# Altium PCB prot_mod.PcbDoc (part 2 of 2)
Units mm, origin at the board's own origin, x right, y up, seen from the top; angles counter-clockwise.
Board outline 113 x 90 mm, 2 copper layers (Top Layer, Bottom Layer), stack 1.562 mm thick; 112 components, 43 nets, 249 pads, 37 vias.
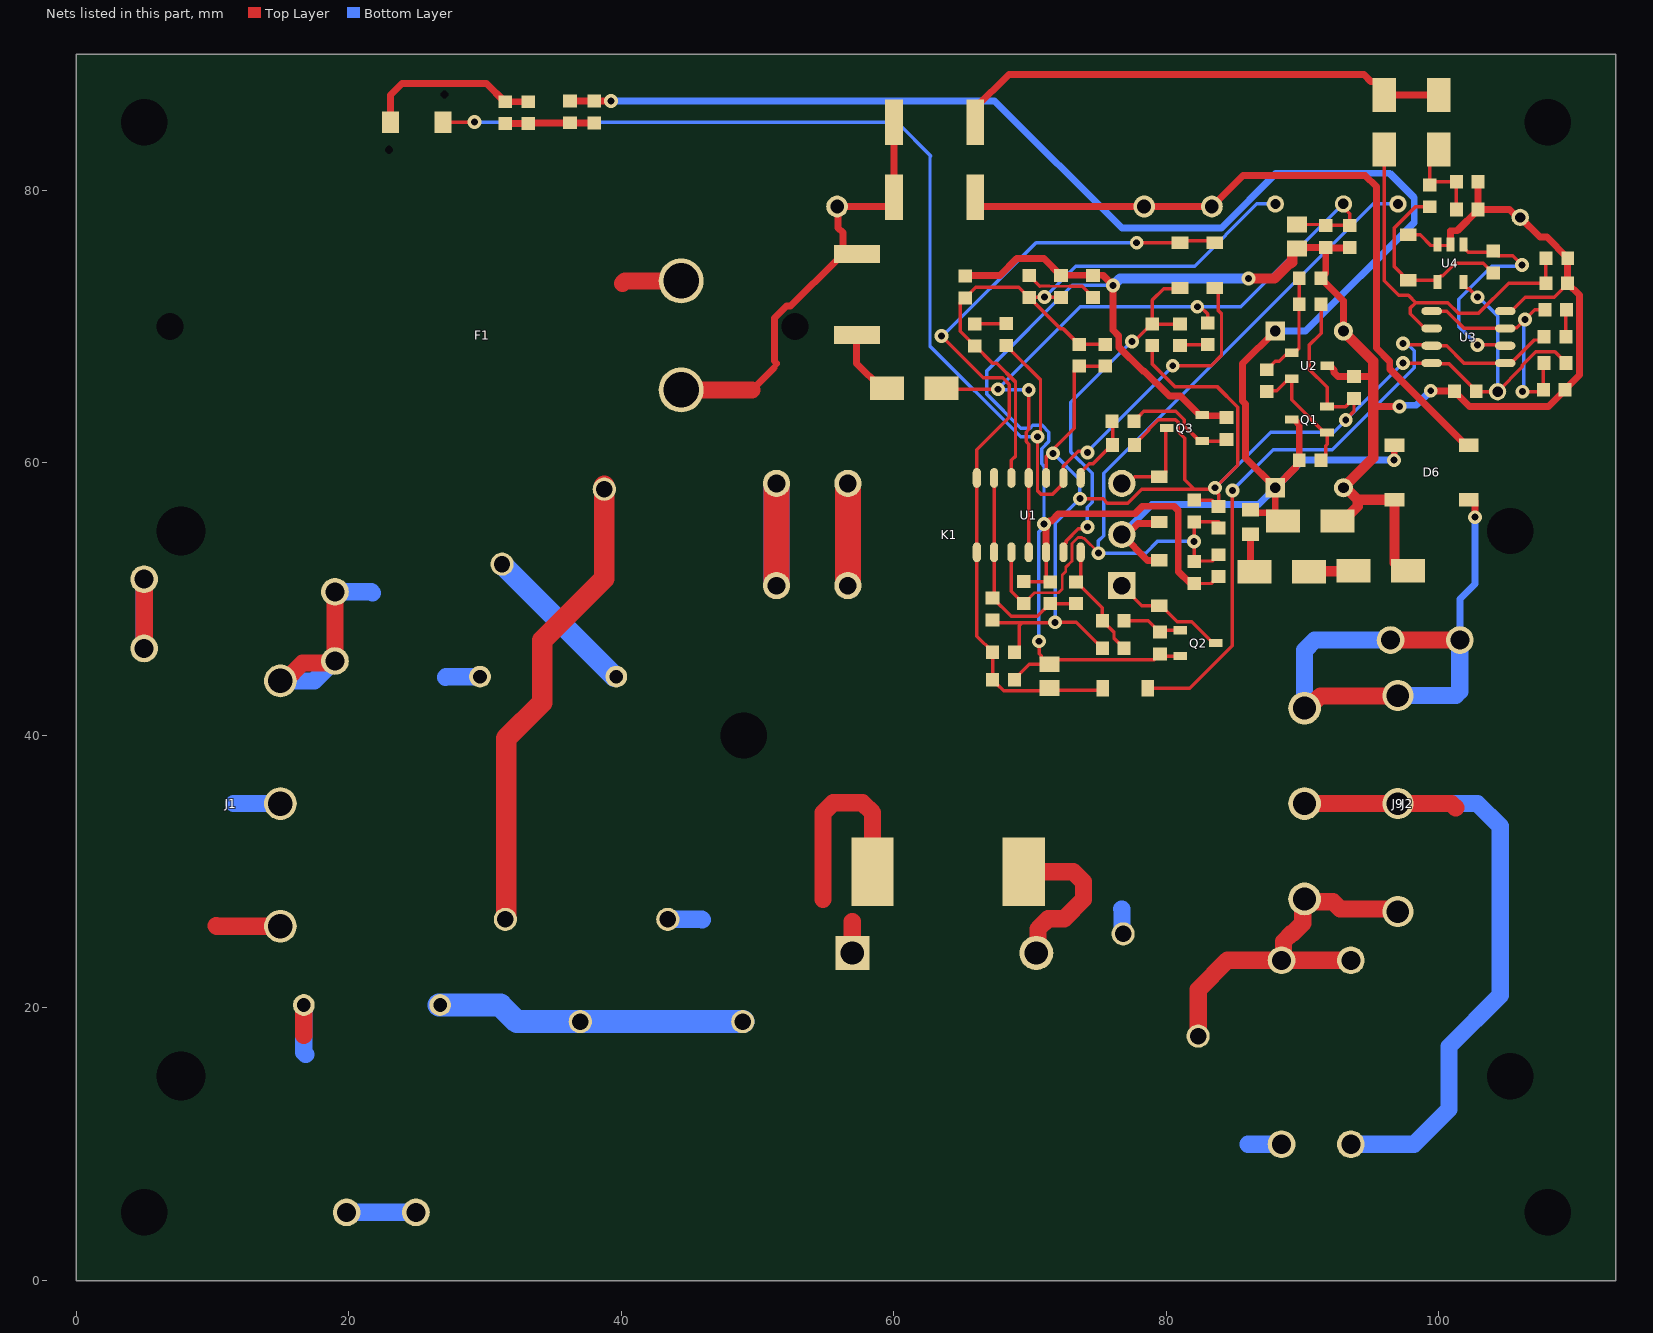
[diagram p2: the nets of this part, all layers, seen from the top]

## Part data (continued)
RV1 RV2 RV3 RV4: library part CMP-PROT-00005-2, "Thermally Protected Varistor 300 V RMS 775 V Clamp 10000 A 800 pF Radial Lead", Varistor Voltage=517V, Voltage Rating (AC)=300V
TP9 TP12 TP13 TP15 TP16: library part NOBOM-00007, "Test point, TH, 0.78mm (30mil) hole, 1.27mm (50 mil) pad", Manufacturer="New Horizons"
U1: library part CMP-ICANA-00000-1, "Quad low-power industrial grade standard comparator 14-SOIC -40 to 85", Case/Package=SOIC, Max Supply Voltage=30V, Min Supply Voltage=3V
U2: library part CMP-ICPWR-00000-1, "V-Ref Adjustable 1.24V to 24V 100mA 3-Pin SOT-23 T/R", Case/Package=SOT-23-3, Max Supply Voltage=25V, Tolerance=0.25%
U3: library part CMP-ICANA-00001-1, "Micropower CMOS dual voltage comparator, 9µA, 16V, -40, 0 to 125, 70°C, SO-8, Tape and Reel", Case/Package=SOIC, Max Supply Voltage=16V, Min Supply Voltage=2.7V
U4: library part CMP-ICANA-00002-2, "Op Amp Single Low Power Amplifier R-R I/O ±8V/16V 5-Pin SOT-23 T/R", Case/Package=SOT-23-5, Max Supply Voltage=16V, Min Supply Voltage=2.5V
Z1 Z6 Z7: library part CMP-NOBOM-00000-1, "Fiducial 1 mm copper, 3 mm solder mask, two footprint options."

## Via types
v1: diameter 1.016, hole 0.508, Top Layer to Bottom Layer, tented both sides, 36 vias
v2: diameter 1.6, hole 1.029, Top Layer to Bottom Layer, 1 vias

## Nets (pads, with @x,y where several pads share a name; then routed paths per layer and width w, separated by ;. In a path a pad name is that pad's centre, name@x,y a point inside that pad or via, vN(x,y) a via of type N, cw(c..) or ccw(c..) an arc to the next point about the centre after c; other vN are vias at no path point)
GND: GDT2.2 J1.3 J2.3 J7.1 J8.1 J9.3 | length 73.8
  Top Layer w1.27: 16.716,18 GDT2.2@16.716,20.216 ; J2.3@90.15,35 J9.3@97,35 100.926,35 101.242,34.683
  Bottom Layer w1.27: 11.564,35 J1.3@15,35 ; GDT2.2@16.716,20.216 16.716,16.738 16.862,16.592 ; J8.1@19.862,5 J8.1@24.942,5 ; 85.992,10 J7.1@88.46,10 ; J2.3@90.15,35 J9.3@97,35 102.843,35 104.518,33.325 104.518,20.941 100.75,17.174 100.75,12.573 98.177,10 J7.1@93.54,10
GND_PROT: C1.2 C12.2 C15.2 C16.2 C25.2 C119.2 C120.2 C121.2 C122.2 C123.2 C124.- C125.- D6.- D8.A D20.A D22.A Q2.2 Q3.2 R6.2 R9.2 R15.2 R17.1 R21.2 R24.1 R28.2 R31.2 R39.2 R44.2 R47.2 R64.2 TP12.1 U1.12 U2.3 U3.4 U4.2 U4.3 | length 204.6
  Top Layer w0.229: C120.2@65.251,73.673 C120.2@65.34,73.762
  Top Layer w0.254: C122.2@68.855,44.098 68.855,44.124 69.96,45.229 C1.2@71.423,45.229 ; C121.2@69.538,51.293 R9.2@71.469,51.293 ; v1(70.67,46.909) 70.67,45.982 70.815,45.837 70.815,45.682 C1.2@71.19,45.307 ; U1.12@71.18,54.133 U1.12@71.18,53.44 71.18,51.581 R9.2@71.469,51.293 ; R9.2@71.496,51.265 R9.2@71.469,51.293 ; C1.2@71.96,45.562 79.107,45.562 79.368,45.822 Q2.2@81.346,45.822 ; R15.2@72.25,73.767 R15.2@72.592,73.767 ; R28.2@82.046,51.149 83.303,51.149 83.811,51.657 R31.2@83.836,51.657 ; D20.A@97.747,76.725 98.633,76.725 99.407,75.951 U4.2@100.856,75.951 ; U3.4@104.876,71.133 105.306,71.133 106.33,72.157 108.474,72.157 C16.2@109.105,72.788
  Top Layer w0.508: C120.2@65.34,73.762 67.791,73.762 69.028,74.999 71.018,74.999 R15.2@72.25,73.767 ; U1.12@71.18,54.133 71.18,55.52 v1@71.403,55.742 ; 71.57,55.742 72.095,56.267 77.696,56.267 78.245,56.816 80.583,56.816 80.881,56.518 80.881,52.018 R28.2@81.765,51.134 ; R15.2@72.592,73.767 75.348,73.767 v1(76.096,73.019) 76.096,69.734 76.513,69.316 76.513,68.514 78.277,66.751 78.374,66.751 80.228,64.896 81.044,64.896 82.393,63.547 82.593,63.547 82.685,63.455 84.29,63.455 R24.1@84.421,63.325 ; C123.2@90.101,75.791 R44.2@91.705,75.791 ; R44.2@91.705,75.816 R44.2@91.705,75.791 ; U2.3@91.8,67.125 92,67.125 92.302,66.822 92.302,66.622 92.6,66.325 C119.2@93.775,66.325 95.051,66.325 95.201,66.175 ; C124.-@93,69.669 93,71.894 91.36,73.534 R6.2@91.36,73.559 91.36,73.584 91.705,73.929 R44.2@91.705,75.765 ; C15.2@93.383,75.765 R44.2@91.705,75.765 ; 95.201,63.98 95.354,64.133 v1(97.127,64.133) ; v1(99.407,65.291) 99.429,65.269 101.125,65.269 C25.2@101.147,65.247 101.147,65.222 102.237,64.133 108.058,64.133 109.274,65.349 R64.2@109.274,65.374 109.274,65.399 110.31,66.435 110.31,72.303 109.453,73.161 C16.2@109.453,73.186 109.456,73.189 109.456,75.005 R47.2@109.459,75.008 109.459,75.033 107.932,76.561 107.428,76.561 TP12.1@105.975,78.014 105.769,78.014 105.194,78.588 C12.2@102.887,78.588 ; U4.2@100.856,75.951 U4.2@100.856,76.026 100.856,77.031 101.354,77.031 102.887,78.563 C12.2@102.887,78.588 ; R39.2@102.887,80.62 C12.2@102.887,78.588 ; R44.2@91.705,75.765 R44.2@91.705,75.791
  Top Layer w0.762: v1(86.035,73.526) 87.93,73.526 89.055,74.651 89.156,74.651 89.237,74.731 89.237,75.542 89.436,75.741 C123.2@89.591,75.741 ; C123.2@89.591,75.791 C123.2@90.101,75.791 ; D22.A@92.56,55.743 92.96,55.743 94.043,56.826 94.043,57.304 ; C124.-@93,69.669 95.201,67.468 95.201,66.175 95.201,63.98 95.201,60.376 C125.-@93,58.175 93.173,58.175 94.043,57.304 ; D8.A@97.748,52.087 97.348,52.087 96.751,52.684 D6.-@96.751,57.304 94.043,57.304
  Bottom Layer w0.254: v1@70.628,46.909 70.628,54.899 71.028,55.299 v1(71.028,55.505) 71.028,59.773 70.878,59.923 70.878,60.345 70.867,60.356 70.867,61.047 71.388,61.569 71.388,62.261 70.899,62.75 70.207,62.75 70.008,62.55 69.32,62.55 66.813,65.056 66.813,66.721 73.11,73.019 v1(76.096,73.019)
  Bottom Layer w0.508: v1(97.127,64.133) 97.224,64.23 98.346,64.23 v1(99.407,65.291)
  Bottom Layer w0.762: v1(76.096,73.019) 76.603,73.526 v1(86.035,73.526)
input_ok: C1.1 C122.1 D3.A D4.A D5.A R5.2 U1.7 U1.8 | length 61.7
  Top Layer w0.254: v1(63.5,69.319) 66.581,66.237 67.994,66.237 68.483,65.748 68.483,63.352 66.1,60.969 U1.7@66.1,58.89 ; U1.7@66.1,58.565 U1.8@66.1,53.44 66.1,47.284 67.255,46.13 R5.2@67.255,46.105 ; R5.2@67.255,45.953 67.255,44.074 67.603,43.726 67.619,43.726 68.073,43.272 71.215,43.272 C1.1@71.423,43.479 ; C1.1@71.423,43.302 75.18,43.302 D4.A@75.332,43.454 ; D5.A@83.8,76.262 83.8,76.287 81.142,76.287 D3.A@81.006,76.151 v1(77.831,76.151) ; v1(77.831,76.151) 77.831,75.853 77.682,76.002 77.649,76.036 77.764,76.151 v1(77.831,76.151)
  Bottom Layer w0.254: v1(63.5,69.319) 63.61,69.319 70.442,76.151 v1(77.831,76.151)
L2: J2.1 J3.1 J9.1 L1.2 L2.2 RV2.1 | length 40
  Top Layer w1.27: L1.2@69.55,30 73.177,30 73.921,29.256 73.921,27.958 72.508,26.546 71.335,26.546 70.591,25.802 70.591,24.163 L2.2@70.464,24.036 ; RV2.1@82.338,17.934 82.338,21.35 84.488,23.5 J3.1@88.46,23.5 ; J3.1@93.54,23.5 J3.1@88.46,23.5 ; J9.1@97,27.075 96.816,27.259 92.76,27.259 92.236,27.784 90.366,27.784 J2.1@90.15,28 90.023,27.873 90.023,26.221 89.279,25.477 89.204,25.477 88.606,24.879 88.606,23.646 J3.1@88.46,23.5
LFUSED: C5.1 F1.1 K1.NO R2.1 R3.1 R10.1 RV1.2 RV3.1 | length 82.7
  Top Layer w0.508: 49.599,65.35 51.226,66.977 ; 51.416,67.295 51.246,67.465 51.246,70.623 52.127,71.504 52.439,71.504 55.864,74.929 56.265,74.929 R3.1@56.661,75.325 ; R3.1@57.303,75.325 56.972,75.325 R3.1@56.661,75.325 ; R10.1@60.025,85 R2.1@60.025,79.5 60.025,79.205 59.629,78.809 C5.1@55.85,78.809 55.928,78.731 55.928,77.247 56.265,76.91 56.265,75.721 R3.1@56.661,75.325
  Top Layer w1.27: F1.1@44.4,65.35 49.599,65.35
  Top Layer w1.524: RV3.1@31.538,26.469 31.538,26.658 31.563,26.683 31.563,39.778 34.207,42.422 34.207,46.969 38.762,51.524 RV1.2@38.762,58.297
  Top Layer w1.905: K1.NO@51.398,58.493 K1.NO@51.398,50.993 K1.NO@51.416,50.975
  Bottom Layer w1.905: K1.NO@51.398,50.993 K1.NO@51.398,58.493
LINE: F1.2 J1.1 J4.1 | length 19.3
  Top Layer w1.27: J4.1@5,46.381 J4.1@5,51.461 ; 10.285,26.04 10.324,26 J1.1@15,26 ; 40.093,73.162 40.28,73.35 F1.2@44.4,73.35
  Bottom Layer w1.27: J4.1@5,46.381 J4.1@5,51.461
LPROT: K1.COM L1.1 L2.1 | length 32.4
  Top Layer w0.254: 56.964,26.342 57.122,26.5
  Top Layer w1.27: 54.819,27.978 54.819,34.324 55.563,35.068 57.706,35.068 58.45,34.324 L1.1@58.45,30 ; L2.1@56.964,24.036 56.964,26.342
  Top Layer w1.905: K1.COM@56.638,50.993 K1.COM@56.638,58.493
  Bottom Layer w1.905: K1.COM@56.638,50.993 K1.COM@56.638,58.493
NC.MOV5: GDT2.1 RV3.2 RV4.2 | length 22.8
  Bottom Layer w1.7: GDT2.1@26.629,20.215 31.139,20.215 32.354,19 RV3.2@37.004,19 RV4.2@48.926,19
NetC5_2: C5.2 D6.AC1 R2.2 | length 53.1
  Top Layer w0.508: R2.2@65.975,79.5 65.975,79.205 66.371,78.809 v2(78.384,78.809) C5.2@83.35,78.809 85.641,81.1 94.6,81.1 95.419,80.281 95.419,73.114 95.435,73.098 95.435,68.415 96.401,67.449 96.401,66.879 101.976,61.304 D6.AC1@102.201,61.304
NetC6_2: C6.2 Q2.1 R17.2 | length 4.9
  Top Layer w0.254: C6.2@76.908,48.446 C6.2@76.908,48.421 78.669,48.421 79.518,47.572 R17.2@79.543,47.572 79.693,47.722 Q2.1@81.346,47.722
NetC7_2: C7.2 Q3.1 R24.2 | length 8.3
  Top Layer w0.254: C7.2@77.632,63.065 77.632,63.09 77.98,63.438 78.005,63.438 78.354,63.787 80.708,63.787 81.32,63.175 81.32,62.72 82.439,61.601 Q3.1@82.639,61.601 84.297,61.601 R24.2@84.421,61.725
NetC118_1: C118.1 Q1.1 R20.1 U2.2 | length 9.6
  Top Layer w0.254: C118.1@87.38,65.234 87.433,65.287 88.112,65.287 89,66.175 U2.2@89.2,66.175 89.2,64.624 91.6,62.225 Q1.1@91.8,62.225 91.8,61.356 91.708,61.264 91.708,60.544 R20.1@91.36,60.196
NetC118_2: C118.2 R6.1 R13.2 U2.1 | length 8.2
  Top Layer w0.254: C118.2@87.38,66.834 87.405,66.834 87.753,67.182 87.753,67.207 88.003,67.456 88.293,67.456 88.739,67.902 89.227,67.902 89.74,68.415 89.74,71.631 R13.2@89.76,71.652 R6.1@89.76,73.559
NetD8_K: D8.K D9.A | length 3.3
  Top Layer w0.762: D9.A@90.476,52.013 90.513,52.05 93.711,52.05 D8.K@93.748,52.087
NetD9_K: D9.K R181.2 | length 2.9
  Top Layer w0.508: R181.2@86.179,54.76 86.179,52.311 D9.K@86.476,52.013
NetD20_K: D20.K R50.2 R59.1 U4.4 | length 15.2
  Top Layer w0.254: R50.2@99.331,78.795 98.288,78.795 96.714,77.221 96.714,74.439 97.265,73.888 97.265,73.736 97.595,73.405 D20.K@97.747,73.405 99.852,73.405 99.906,73.351 99.906,73.501 100.129,73.724 100.279,73.724 101.206,74.651 101.681,74.651 103.26,74.651 103.975,73.935 R59.1@104,73.935 R59.1@104.292,73.643
NetD57_A: D57.A R3.2 | length 5
  Top Layer w0.254: D57.A@59.1,65.477 D57.A@59.5,65.477
  Top Layer w0.508: R3.2@57.282,69.354 57.282,67.295 D57.A@59.1,65.477
NetD58_A: D58.A D59.K R10.2 | length 36.9
  Top Layer w0.508: R10.2@65.975,85 65.975,86.025 68.45,88.5 94.5,88.5 95.004,87.996 95.404,87.996 96,87.4 D58.A@96,87 D59.K@100,87
NetD60_A: D60.A R48.2 R49.2 | length 13
  Top Layer w0.508: D60.A@23.068,85 23.068,87 23.909,87.841 30.117,87.841 31.461,86.497 R48.2@31.486,86.497 R49.2@33.171,86.497
NetGDT1_2: GDT1.2 RV1.1 | length 11.8
  Bottom Layer w1.524: RV1.1@31.263,52.567 39.503,44.326 39.63,44.326 GDT1.2@39.645,44.312
NetR4_1: R4.1 R8.1 | length 2.3
  Top Layer w0.254: R4.1@65.956,70.179 R4.1@65.981,70.179 ; R4.1@65.956,70.211 R8.1@68.258,70.211
NetR7_2: R7.2 R9.1 R12.1 U1.6 U1.9 | length 16
  Top Layer w0.254: U1.6@67.37,58.959 67.37,50.197 R7.2@67.255,50.081 67.28,50.081 68.629,48.732 70.538,48.732 71.471,49.665 R9.1@71.496,49.665 R12.1@73.376,49.665
NetR11_1: R11.1 R21.1 | length 5.2
  Top Layer w0.203: 70.717,72.956 70.722,72.956 70.742,72.976 71.413,72.976 71.433,72.956 72.907,72.956
  Top Layer w0.254: R11.1@70.052,73.622 70.717,72.956 ; 72.907,72.956 72.913,72.95 73.841,72.95 R21.1@74.624,72.167
NetR26_1: R26.1 R27.2 | length 2.1
  Top Layer w0.254: R26.1@81.007,68.597 81.084,68.673 R27.2@83.039,68.673
NetR48_1: R48.1 R49.1 R52.2 R56.2 | length 6.6
  Top Layer w0.508: R48.1@31.486,84.897 R49.1@33.171,84.897 33.201,84.928 36.22,84.928 R56.2@36.25,84.958 ; R56.2@36.25,84.943 R52.2@38.014,84.943
NetR54_1: R54.1 R58.1 | length 2.1
  Top Layer w0.254: R58.1@109.325,69.133 R58.1@109.381,69.189 ; R58.1@109.325,69.267 109.325,71.165 R54.1@109.381,71.221
NEUT: D6.AC2 GDT1.1 J1.2 J2.2 J5.1 J6.1 J9.5 RV2.2 RV4.1 | length 66.5
  Top Layer w0.508: D6.AC2@102.656,57.208 102.659,57.205 102.659,56.016 v1(102.663,56.013)
  Top Layer w1.27: J1.2@15,44 15.306,44 16.62,45.314 18.854,45.314 J6.1@19,45.46 J6.1@19,50.54 ; J2.2@90.15,42 90.421,42 91.313,42.893 96.968,42.893 J9.5@97,42.925 ; J5.1@96.46,47 J5.1@101.54,47
  Bottom Layer w0.508: 101.242,42.925 101.54,43.222 ; J5.1@101.54,47 101.54,50 102.663,51.123 v1(102.663,56.013) v1@102.8,56.013
  Bottom Layer w1.27: J1.2@15,44 17.475,44 18.935,45.46 J6.1@19,45.46 ; J6.1@19,50.54 21.655,50.54 21.75,50.445 ; 27.116,44.277 27.152,44.312 GDT1.1@29.645,44.312 ; RV4.1@43.426,26.5 45.925,26.5 45.956,26.469 ; 76.738,27.26 76.756,27.242 76.756,25.516 RV2.2@76.838,25.434 ; J2.2@90.15,42 90.15,46.256 90.894,47 J5.1@96.46,47 ; J9.5@97,42.925 101.242,42.925 ; 101.54,43.222 J5.1@101.54,47
overvoltage#: D5.K D60.K R8.2 U1.2 | length 96.7
  Top Layer w0.254: D60.K@26.932,85 v1(29.25,85) ; R8.2@68.258,68.611 68.283,68.611 68.631,68.263 68.631,68.238 70.773,66.096 70.773,62.134 v1(70.553,61.915) 70.553,57.953 70.795,57.712 71.678,57.712 72.45,58.484 U1.2@72.45,58.565 ; U1.2@72.45,58.959 72.45,59.74 73.553,60.843 74.136,60.843 v1(74.212,60.768) ; v1(80.476,67.125) 83.292,67.125 84.054,67.887 84.054,70.935 83.8,71.189 83.8,72.812 D5.K@83.683,72.694
  Bottom Layer w0.254: v1(29.25,85) 60.25,85 62.733,82.517 62.665,82.449 62.665,68.562 69.313,61.915 v1(70.553,61.915) ; v1(74.212,60.768) 74.212,60.814 80.476,67.078 v1(80.476,67.125)
peak_neg: C12.1 D59.A R39.1 R50.1 | length 7
  Top Layer w0.254: D59.A@100,83 99.331,82.331 R50.1@99.331,80.395 99.557,80.62 R39.1@101.287,80.62 C12.1@101.287,78.563
peak_neg_inv: R59.2 U3.2 U4.1 | length 16.1
  Top Layer w0.254: U4.1@101.806,75.951 101.806,75.801 102.156,75.451 R59.2@103.677,75.451 ; v1(102.841,68.651) 102.845,68.655 104.991,68.655 U3.2@104.995,68.658 ; R59.2@104,75.535 104.348,75.187 105.438,75.187 v1(106.102,74.524)
  Bottom Layer w0.254: 101.447,72.003 101.447,70.044 v1(102.841,68.651) ; 101.466,72.02 103.693,74.248 103.884,74.439 v1@105.779,74.439
peak_out: D4.K R58.2 U3.1 U3.7 | length 49.1
  Top Layer w0.254: D4.K@78.652,43.454 81.712,43.454 84.85,46.592 v1(84.85,57.97) ; v1(97.363,68.767) 97.471,68.659 99.41,68.659 U3.7@99.476,68.593 ; U3.7@99.776,68.593 100.576,68.593 101.846,67.323 U3.1@104.576,67.323 ; U3.1@104.995,67.388 105.043,67.436 105.439,67.436 107.018,69.015 107.473,69.015 R58.2@107.565,69.107
  Bottom Layer w0.254: v1(84.85,57.97) 87.85,60.97 92.191,60.97 98.198,66.977 98.198,68.223 97.659,68.762 97.368,68.762 v1(97.363,68.767)
peak_pos: C16.1 D58.K R47.1 U3.6 | length 28.2
  Top Layer w0.254: D58.K@96,83 96,73.355 97.068,72.286 97.776,72.286 98.302,71.76 ; U3.6@99.476,69.863 98.976,69.863 97.909,70.93 97.909,71.367 98.302,71.76 ; C16.1@107.853,72.97 C16.1@107.859,72.976 ; R47.1@107.853,75.002 C16.1@107.853,73.186 105.132,73.186 102.94,70.993 101.428,70.993 100.661,71.76 98.302,71.76
peak_thresh: R54.2 R62.2 R64.1 U3.3 U3.5 | length 17.4
  Top Layer w0.254: U3.5@99.776,71.133 100.576,71.133 101.846,69.863 U3.3@104.576,69.863 ; U3.3@105.059,69.864 105.104,69.909 105.716,69.909 v1(106.33,70.523) 107.028,71.221 R54.2@107.781,71.221 ; v1(106.132,65.222) R64.1@107.522,65.222 ; R64.1@107.675,65.241 R64.1@107.725,65.291 ; R64.1@107.675,65.374 R62.2@107.675,67.273
  Bottom Layer w0.254: v1(106.132,65.222) 106.231,65.321 106.231,70.424 v1(106.33,70.523)
PROT_RESET: D1.A K1.RESET Q2.3 | length 8.6
  Top Layer w0.254: K1.RESET@76.738,50.993 78.204,49.527 D1.A@79.474,49.527 79.626,49.527 80.804,48.349 81.86,48.349 83.437,46.772 Q2.3@83.637,46.772
PROT_SET: D2.A K1.SET Q3.3 | length 6.8
  Top Layer w0.254: K1.SET@76.738,58.493 77.195,58.493 77.682,58.98 79.628,58.98 79.958,59.31 79.958,62.47 Q3.3@80.039,62.551
ref_high: C120.1 R4.2 R11.2 R15.1 R19.2 R23.2 TP9.1 U1.5 | length 50.1
  Top Layer w0.254: U1.5@68.64,58.89 68.64,60.196 68.937,60.492 68.937,65.936 67.563,67.311 67.249,67.311 65.981,68.579 R4.2@65.956,68.579 65.931,68.579 65.583,68.927 65.583,68.952 64.878,69.656 64.878,71.763 65.226,72.111 C120.1@65.251,72.111 66.031,72.891 69.183,72.891 R11.2@69.938,72.136 72.25,69.824 72.458,69.824 73.596,68.687 73.607,68.698 R19.2@73.609,68.698 R23.2@75.514,68.698 ; R11.2@70.052,72.37 70.255,72.167 v1(71.077,72.167) R15.1@72.592,72.167
  Bottom Layer w0.254: v1(71.077,72.167) 73.35,74.439 82.079,74.439 86.64,79 TP9.1@88,79
ref_low: C121.1 R28.1 R29.2 R31.1 R32.2 TP13.1 U1.10 | length 63.5
  Top Layer w0.203: C121.1@69.538,49.693 69.563,49.693 70.335,50.465 72.098,50.465 72.362,50.729 72.362,51.751 72.626,52.015 72.626,52.34 73.074,52.788 73.074,54.07 73.522,54.518 73.827,54.518 73.878,54.467 73.97,54.467 75.021,53.415 v1(75.021,53.371)
  Top Layer w0.254: U1.10@68.64,53.44 68.64,50.565 69.513,49.693 C121.1@69.538,49.693 ; R31.1@83.836,53.257 83.379,52.8 82.046,52.8 v1(82.046,54.235) R29.2@82.046,55.67 R32.2@83.836,55.67
  Bottom Layer w0.254: v1(82.046,54.235) 79.355,54.235 78.491,53.371 v1(75.021,53.371) 75.021,54.269 75.411,54.659 75.411,59.224 95.187,79 TP13.1@97,79
reset: C6.1 R12.2 R16.2 U1.14 | length 8.7
  Top Layer w0.254: U1.14@73.72,53.44 73.72,51.61 R12.2@73.376,51.265 73.401,51.265 75.308,49.358 C6.1@75.308,48.421 76.165,47.564 76.165,47.132 R16.2@76.908,46.389
sense_prot: C15.1 C123.1 D57.K R27.1 R44.1 TP16.1 U1.4 U1.11 | length 56.5
  Top Layer w0.254: D57.K@63.5,65.477 63.575,65.402 v1(67.648,65.402) ; U1.11@69.91,53.371 U1.4@69.91,58.565 ; U1.4@69.91,58.959 69.91,61.377 69.718,61.569 69.718,62.261 69.91,62.453 v1(69.91,65.35) ; v1(82.277,71.454) 82.506,71.454 83.039,70.921 R27.1@83.039,70.273 ; C123.1@89.591,77.491 91.63,77.491 R44.1@91.705,77.416 R44.1@91.705,77.466 ; R44.1@91.933,77.441 C15.1@93.457,77.441 ; TP16.1@93,79 93,78.725 93.457,78.268 C15.1@93.457,77.441 ; C15.1@93.457,77.405 C15.1@93.457,77.441 ; C15.1@93.682,77.441 C15.1@93.457,77.441
  Bottom Layer w0.254: v1(69.91,65.35) 69.884,65.376 67.674,65.376 v1(67.648,65.402) 73.688,71.443 v1@82.277,71.443 ; v1(82.277,71.454) 85.454,71.454 TP16.1@93,79
set: C7.1 R18.2 U1.1 | length 5.3
  Top Layer w0.254: U1.1@73.72,58.89 73.72,59.315 74.338,59.933 74.626,59.933 R18.2@76.006,61.313 ; C7.1@76.032,63.065 76.057,63.04 R18.2@76.057,61.313
undervoltage#: D3.K R25.1 R26.2 U1.13 | length 27.1
  Top Layer w0.254: U1.13@72.45,53.371 72.45,53.959 72.645,54.154 72.645,54.247 73.551,55.153 74.066,55.153 v1(74.212,55.299) ; v1(77.475,68.913) 77.666,68.913 78.95,70.197 R25.1@78.975,70.197 78.975,71.95 79.812,72.787 80.625,72.787 D3.K@80.625,72.812 ; R25.1@78.975,70.173 80.983,70.173 R26.2@81.007,70.197
  Bottom Layer w0.254: v1(74.212,55.299) 74.212,56.744 74.567,57.099 74.567,59.232 73.002,60.797 73.002,64.439 v1(77.475,68.913)
VCC_PROT: C25.1 C119.1 Q1.2 R5.1 R7.1 R13.1 R16.1 R18.1 R19.1 R23.1 R25.2 R29.1 R32.1 R62.1 TP15.1 U1.3 U3.8 U4.5 | length 128.6
  Top Layer w0.254: R7.1@67.335,48.401 67.458,48.278 69.436,48.278 ; R5.1@68.855,46.105 69.203,46.453 69.203,48.045 69.436,48.278 ; U1.3@71.18,58.959 71.18,60.483 v1@71.561,60.864 ; v1(71.702,60.702) 71.702,60.724 v1@71.561,60.864 ; R19.1@73.609,67.087 R23.1@75.514,67.087 ; R19.1@73.609,67.098 73.584,67.098 73.236,66.75 73.236,62.539 v1@71.561,60.864 ; v1(73.659,57.372) 75.362,57.372 75.684,57.05 77.181,57.05 78.202,58.071 82.046,58.071 ; R16.1@75.308,46.389 75.308,46.414 74.96,46.762 74.935,46.762 73.397,48.3 v1(71.845,48.3) 71.823,48.278 69.436,48.278 ; R18.1@77.657,61.313 77.657,61.338 78.704,62.385 78.704,62.479 79.404,63.178 80.675,63.178 80.866,62.986 80.866,62.294 81.35,61.81 81.35,58.767 82.046,58.071 ; R25.2@78.975,68.597 78.975,67.251 80.625,65.601 83.726,65.601 85.248,64.079 85.248,59.838 v1(83.582,58.172) 83.582,57.966 83.836,57.712 R32.1@83.836,56.813 83.811,56.813 83.354,57.27 R29.1@82.046,57.27 ; R29.1@81.97,57.372 R29.1@82.046,57.372 ; v1@83.296,58.071 82.046,58.071 ; R13.1@91.36,71.652 91.36,69.521 90.476,68.637 90.476,66.879 91.8,65.555 Q1.2@91.8,64.125 93.15,64.125 93.75,64.725 C119.1@93.775,64.725 93.775,63.787 93.173,63.185 v1(93.173,63.133) ; R13.1@91.411,71.652 R13.1@91.576,71.817 ; v1(97.363,67.323) U3.8@99.476,67.323 ; U3.8@99.776,67.323 99.842,67.257 100.762,67.257 102.747,65.272 C25.1@102.747,65.247 102.773,65.222 TP15.1@104.314,65.222 106.132,67.039 ; U4.5@101.806,73.012 101.87,73.012 102.096,72.786 102.216,72.786 v1(102.845,72.157) ; 106.132,67.167 107.114,68.15 108.523,68.15 R62.1@109.325,67.348
  Bottom Layer w0.254: v1(71.702,60.702) 71.724,60.702 73.659,58.767 v1(73.659,57.372) 71.863,55.576 71.863,48.318 v1(71.845,48.3) ; v1(83.582,58.172) 87.661,62.251 92.291,62.251 v1(93.173,63.133) v1(97.363,67.323) ; v1(102.845,72.157) 102.932,72.157 104.314,70.776 TP15.1@104.314,65.222
VCOIL: C124.+ C125.+ D1.K D2.K D6.+ D22.K K1.PLUS Q1.3 R20.2 R52.1 R56.1 R181.1 | length 137.7
  Top Layer w0.508: R56.1@36.25,86.543 R52.1@38.014,86.543 ; R52.1@38.039,86.543 R52.1@38.014,86.543 ; v1(39.25,86.558) 39.243,86.551 38.021,86.551 R52.1@38.014,86.543 ; D1.K@79.474,52.847 78.634,52.847 K1.PLUS@76.738,54.743 77.142,54.743 77.941,55.542 79.358,55.542 D2.K@79.475,55.66 ; R181.1@86.179,56.56 86.399,56.339 87.964,56.339 D22.K@88,56.303 ; C124.+@88,69.669 85.608,67.277 85.608,64.541 85.829,64.32 85.829,60.346 C125.+@88,58.175 ; D22.K@88.56,55.743 D22.K@88,56.303 ; Q1.3@89.2,63.175 89.4,63.175 89.76,62.814 R20.2@89.76,60.196 89.539,59.975 89.539,59.714 C125.+@88,58.175 ; v1(96.714,60.196) 96.732,60.214 D6.+@96.732,61.304 ; D22.K@88,56.303 C125.+@88,58.175
  Bottom Layer w0.508: v1(39.25,86.558) 67.401,86.558 76.738,77.221 84.039,77.221 88.068,81.25 96.401,81.25 98.198,79.453 98.198,77.649 90.218,69.669 C124.+@88,69.669 ; K1.PLUS@76.738,54.743 78.938,56.943 86.769,56.943 C125.+@88,58.175 90.021,60.196 v1(96.714,60.196)
pads on no net: F1.M1 F1.M2 J1.ML J1.MN J2.ML J2.MN MECH1.1 MECH1.2 MH1.1 MH2.1 MH3.1 MH4.1 MH5.1

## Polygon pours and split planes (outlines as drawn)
NEUT on Bottom Layer "BOT_NEUT" (solid, remove dead copper, pour order 0): 111.044,52.957 75.095,52.957 75.053,47.795 67.055,39.977 39.582,40.028 30.041,48.031 29,49 27.379,53.111 12.105,53.111 12.105,42.025 20.234,42.025 34.921,20 81.704,20 84.95,23.246 84.95,34.711 91.167,40.818 110.977,40.721
GND on Bottom Layer "BOT_GND" (solid, remove dead copper, pour order 1): 1,37 19.802,37 35.062,14 80,14 87.964,21.964 87.964,38.184 111,38.184 111,8.203 110.797,8 102,8 95,1 4,1 1,4
L2 on Top Layer "TOP_L2" (solid, pour order 4): 67,20 91.886,20 98.048,26.162 98.048,28 97.006,28 85.992,38.918 85.134,38.918 67,38.918
GND on Top Layer "TOP_GND" (solid, remove dead copper, pour order 6): 1,20 20.999,20 24.98,14 80,14 87.964,21.964 87.964,38.184 111,38.184 111,8.203 110.797,8 102,8 95,1 4,1 1,4
LINE on Top Layer "TOP_LINE" (solid, remove dead copper, pour order 2): 1,23.992 21.277,23.992 26,55 33.039,72 46.913,72 46.913,80 7,80 1,74
LFUSED on Top Layer "TOP_LFUSED" (solid, remove dead copper, pour order 5): 51.898,49 51.898,68 36,68 36,49
LPROT on Top Layer "TOP_LPROT" (solid, remove dead copper, pour order 3): 50,59.78 50,20 63.03,20 62.97,59.78

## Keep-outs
Keep-Out Layer:
  circle w0.254: c49,40 r5
  lines w1.016: 0,10 0,80 5,80 ccw(c5,85) 10,85 10,90 103,90 103,85 ccw(c108,85) 108,80 113,80 113,10 108,10 ccw(c108,5) 103,5 103,0 10,0 10,5 ccw(c5,5) 5,10 0,10

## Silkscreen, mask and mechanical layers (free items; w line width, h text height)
Top Overlay:
  rectangle: 71.126,2.9 85.731,11.155
  region: 79.521,51.783 78.886,50.513 80.156,50.513
  region: 77.627,41.4 76.357,42.035 76.357,40.765
  region: 79.487,56.637 80.122,57.907 78.852,57.907
  region: 85.488,74.735 86.123,76.005 84.853,76.005
  region: 79.027,74.735 79.662,76.005 78.392,76.005
  region: 90.098,58.378 91.368,57.743 91.368,59.013
  region: 94.115,49.488 95.385,48.853 95.385,50.123
  region: 95.682,75.391 96.318,76.661 95.047,76.661
  region: 102.656,85.464 102.021,84.194 103.291,84.194
  region: 93.458,83.865 94.093,85.135 92.823,85.135
  region: 87.05,49.285 88.32,48.65 88.32,49.92
  region: 62.27,62.522 61,63.157 61,61.887
  lines w0.152: 65.75,51.75 68.088,51.75 68.75,51.088 ; 80.293,45.222 80.293,45.102 81.296,44.099
  lines w0.254: 62.27,61.887 62.27,63.157 ; 77.627,40.765 77.627,42.035 ; 78.392,74.735 79.662,74.735 ; 78.852,56.637 80.122,56.637 ; 78.886,51.783 80.156,51.783 ; 84.853,74.735 86.123,74.735 ; 87.05,48.65 87.05,49.92 ; 90.098,57.743 90.098,59.013 ; 92.823,83.865 94.093,83.865 ; 94.115,48.853 94.115,50.123 ; 95.047,75.391 96.317,75.391 ; 102.021,85.464 103.291,85.464 ; 55.084,2.93 67.276,2.93 67.276,11.058 55.084,11.058 55.084,2.93
  lines w0.5: 26.347,1.203 27.145,2.5 28.653,2.5 ; 27.853,1.2 28.653,2.5 ; 28.653,5 28.653,2.5 ; 29.375,1.186 30.183,2.5 28.653,2.5 ; 88.694,2.203 89.492,3.5 91,3.5 ; 90.2,2.2 91,3.5 ; 91,6 91,3.5 ; 91.722,2.186 92.531,3.5 91,3.5
  text "Sense Prot" at 92.555,80.247 h0.9 r90
  text "High Thresh" at 88.451,80.023 h0.9 r90
  text "LFUSED" at 41.456,55.516 h1.78
  text "L" at 6.9,48.128 h2.03
  text "N" at 20.984,46.969 h2.03
  text "NEUT" at 103.472,46.592 h1.78
  text "LPROT" at 55.925,40.281 h1.78
  text "GND" at 99.301,34.516 h1.78
  text "HV     to GND   : 4.0mm (0.158\")" at 22.484,32.29 h1.78
  text "LINEin to NEUT  : 3.0mm (0.120\")" at 22.484,31.02 h1.78
  text "LINE to LINEPROT: 3.0mm (0.120\")" at 22.484,29.75 h1.78
  text "NEUT to LINEPROT: 1.5mm (0.060\")" at 22.484,28.48 h1.78
  text "L2" at 82.092,25.722 h1.78
  text "LINE" at 5.78,25.5 h1.78
  text "Voltage Protection Module" at 11,13 h1.52
  text "Revision" at 55.084,12.074 h1.52
  text "Serial #" at 72.65,12.044 h1.52
  text "Licensed under CERN-OHL-P v2" at 11.138,10 h1.52
  text "Source package at https://docs.2to8.cc" at 11.138,7 h1.52
  text ".nhProjRev" at 57.908,6.004 h3.05
Bottom Overlay:
  rectangle: 38.19,80.981 52.795,89.236
  lines w0.127: 85.326,69.383 53.8,69.383 53.8,88.309 85.4,88.309 85.4,69.309
  lines w0.254: 30.053,82.307 28.766,82.758 ; 30.053,83.25 28.766,82.758 ; 31.306,82.758 28.766,82.758 ; 8.973,81.119 21.165,81.119 21.165,89.247 8.973,89.247 8.973,81.119
  lines w0.406: 95.1,57.407 95.1,59.185 ; 95.1,68.763 95.1,70.541 ; 95.8,57.407 95.8,59.185 ; 95.8,68.763 95.8,70.541
  lines w0.5: 12.694,7.019 13.492,5.722 15,5.722 ; 14.2,7.022 15,5.722 ; 15,3.222 15,5.722 ; 15.722,7.036 16.531,5.722 15,5.722 ; 82.444,9.623 83.242,8.327 84.75,8.327 ; 83.95,9.626 84.75,8.327 ; 84.75,5.826 84.75,8.327 ; 85.472,9.64 86.281,8.327 84.75,8.327
  text "HighThresh" at 88.453,89.3 h1.27 r90
  text "Sense Prot" at 93.385,89.3 h1.27 r90
  text "Low Thresh" at 97.635,89.3 h1.27 r90
  text "voltage" at 27.713,88.008 h2.03 r180
  text ".nhProjRev" at 12.288,86.072 h3.05 r180
  text "over" at 27.713,85.338 h2.03 r180
  text "Revision" at 11.025,80.142 h1.52 r180
  text "Serial #" at 41.766,79.937 h1.52 r180
  text "GND" at 108.635,78.55 h1.27 r90
  text "Prot" at 110.635,78.55 h1.27 r90
  text "Vcc" at 108.635,66.05 h1.27 r90
  text "Prot" at 110.635,66.05 h1.27 r90
  text "Neutral" at 106.5,52.25 h2.03 r90
  text "Out (N2)" at 110,52.25 h2.03 r90
  text "NEUT" at 87.665,50.853 h1.78 r180
  text "L" at 7.9,49 h2.03 r180
  text "N" at 22,48.65 h2.03 r180
  text "Line In" at 1.75,43 h2.03 r180
  text "Neutral In" at 13,41.5 h2.03 r180
  text "GND" at 102.536,35.484 h1.78 r180
  text "GND" at 5.99,35.034 h1.78 r180
  text "Line Out (L2)" at 87.144,20.5 h2.03 r180
  text "Ground" at 15.282,12.956 h2.03 r180
  text "Earth" at 15.286,9.908 h2.03 r180
  text "Source package at https://docs.2to8.cc" at 35,7.022 h1.52 r180
  text "Ground" at 86.993,6.842 h2.03 r180
  text "Licensed under CERN-OHL-P v2" at 35,5.022 h1.52 r180
  text "Earth" at 87.144,3.698 h2.03 r180
  text "Voltage Protection Module" at 34.457,2.906 h1.52 r180
Board Outline:
  lines w0.1: 23.925,83.825 23.925,86.175 26.075,86.175 26.075,83.825 23.925,83.825
  lines w0.508: 0,0 0,90 113,90 113,0 0,0
User Drawing:
  circle w0.102: c37.004,19 r2.35
  circle w0.102: c26.714,20.216 r2.35
  circle w0.102: c31.263,52.567 r3.912
  circle w0.102: c15,50 r7.6
  circle w0.102: c16.716,20.216 r8.8
  circle w0.102: c31.504,26.502 r2.35
  circle w0.102: c15,32 r7.6
  circle w0.102: c15,41 r7.6
  circle w0.102: c29.645,44.252 r3.8
  circle w0.102: c39.645,44.252 r3.81
  circle w0.102: c48.926,19.002 r2.35
  circle w0.102: c38.763,58.067 r3.912
  circle w0.102: c95.201,85.5 r3
  circle w0.102: c60.778,83.328 r3
  circle w0.102: c58.953,68.824 r3.889
  circle w0.102: c51.398,58.493 r4
  circle w0.102: c102.731,56.013 r3.048
  circle w0.102: c70.464,32.036 r2.35
  circle w0.102: c59.481,83.2 r3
